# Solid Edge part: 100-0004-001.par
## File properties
Title: Flange
Author: rtconerl
Template: Ansimm.Par
Last saved by: jccrumbl
Revision: 54
Application: Solid Edge
Revision: A
Company: UGS PLM Solutions
Teamcenter Item Type: Item
Accuracy: 0.99
TC Engineering Description: Valve Side Panel
TC_ImportTime: 2008-07-08
PartType: -
Last Saved Version: -
Material: aluminum
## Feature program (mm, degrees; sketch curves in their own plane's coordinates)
pattern "unnamed Pattern 1"
pattern "unnamed Pattern 2"
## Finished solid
Body 1: solid body, 64 faces, 138 edges, 72 vertices.
  Faces by surface: cylinder 32, plane 18, torus 12, cone 1, sphere 1
  Edges by curve: circle 70, line 52, intersection 16
Bounding box of the edges (mm; curved faces can reach further): 90.000 x 90.000 x 50.000, from (-45, -45, -20) to (45, 45, 30).
Cylindrical faces by radius (mm): R1.5 x16, R2 x4, R5 x4, R10 x4, R15 x1, R25 x1, R27.5 x1, R32.5 x1
Conical faces (half-angle, radius in mm at the cone's reference point): 70 deg R34.4727 x1
Toroidal faces (ring radius, tube radius in mm): R3 r1.5 x8, R8 r2 x4
Spherical faces by radius (mm): R30 x1
Planar faces by outward normal: +x 2, +y 2, +z 3, -x 2, -y 2, -z 3, oblique 4
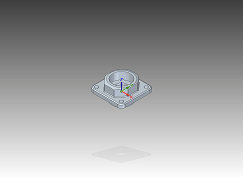
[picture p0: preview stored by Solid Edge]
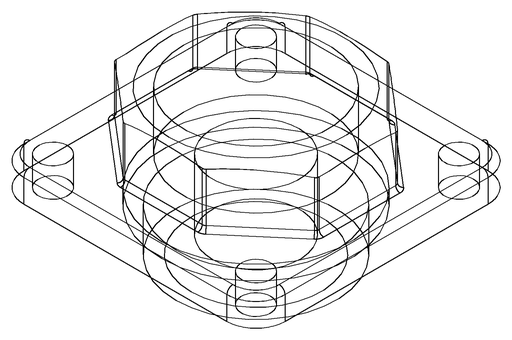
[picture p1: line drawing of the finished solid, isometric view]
